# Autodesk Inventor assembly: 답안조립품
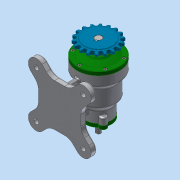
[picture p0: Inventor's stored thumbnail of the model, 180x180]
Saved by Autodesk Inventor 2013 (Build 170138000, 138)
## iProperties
Created: 2017-03
Part Number: 답안조립품
Document SubType Name: Assembly
Designer: dgall
Author: dgall
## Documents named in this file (14)
- C:\Users\dgall\Desktop\470307V1011\답안조립품.iam
- C:\Users\dgall\Desktop\470307V1011\본체.ipt
- C:\Users\dgall\Desktop\470307V1011\뒤커버.ipt
- C:\Users\dgall\Desktop\470307V1011\베어링-6200.ipt
- C:\Users\dgall\Desktop\470307V1011\베어링-6203.ipt
- C:\Users\dgall\Desktop\470307V1011\볼트 M5 x 10.ipt
- 볼트 M5 x 10.ipt
- C:\Users\dgall\Desktop\470307V1011\스프로킷.ipt
- C:\Users\dgall\Desktop\470307V1011\앞커버.ipt
- C:\Users\dgall\Desktop\470307V1011\오일 실 10 20 7.ipt
- C:\Users\dgall\Desktop\470307V1011\오일 실 17 30 8.ipt
- C:\Users\dgall\Desktop\470307V1011\축.ipt
- C:\Users\dgall\Desktop\470307V1011\키5x5.ipt
- C:\Users\dgall\Desktop\470307V1011\볼트 M4 x 12.ipt
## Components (9 placed, 1 different names)
1. ISO 4762 M4 x 12:1
2. ISO 4762 M4 x 12:2
3. ISO 4762 M4 x 12:3
4. ISO 4762 M4 x 12:4
5. ISO 4762 M4 x 12:5
6. ISO 4762 M4 x 12:6
7. ISO 4762 M4 x 12:7
8. ISO 4762 M4 x 12:8
9. ISO 4762 M4 x 12:9
